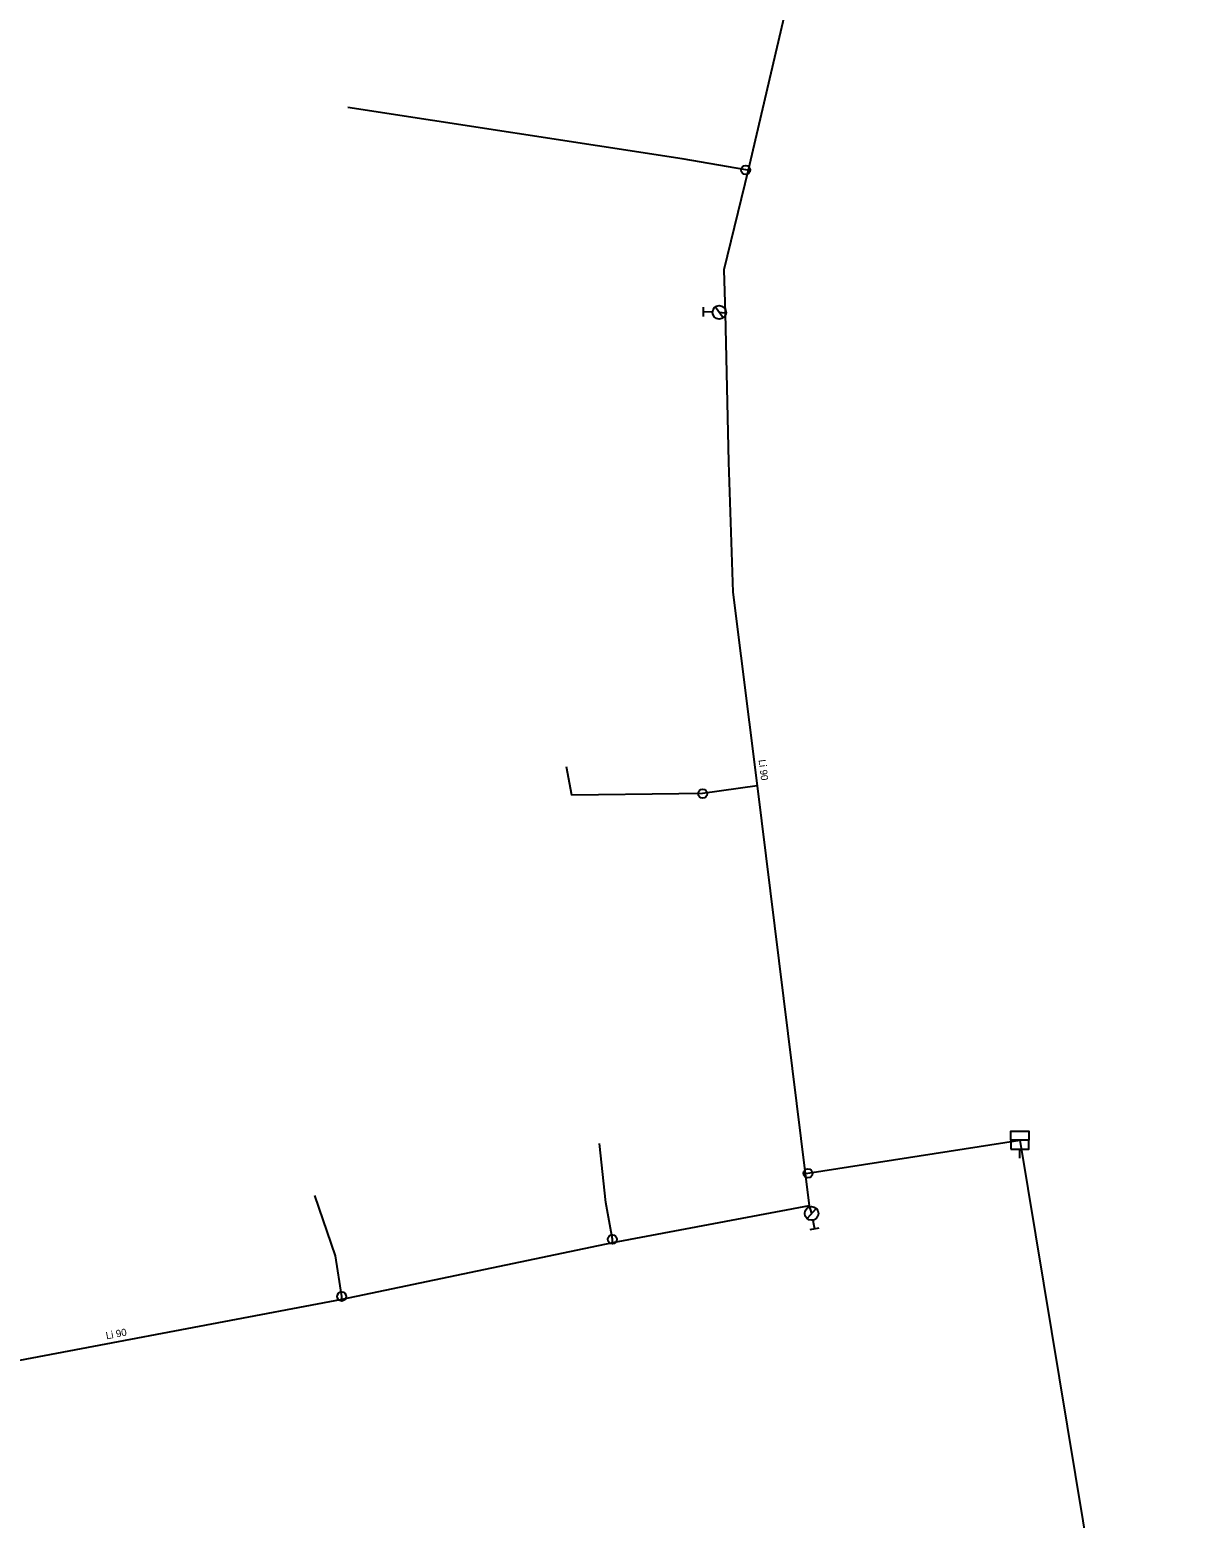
# Model space of a CAD drawing. Extents: x -684835 to -684548, y -1163297 to -1162881.
# Drawn here: x -684770.1 to -684705.3, y -1163230 to -1163147.7 of the extents above; entities that cross this region are included whole.
import ezdxf

# ---------------------------------------------------------------- set-up
doc = ezdxf.new("R2010")
doc.units = 0
for name, color, linetype in [('Hydranty', 7, 'Continuous'), ('Popis vodovodních řadů', 7, 'Continuous'), ('Vod přípojky-voda pitná', 7, 'Continuous'), ('Vodovodní řad', 7, 'Continuous'), ('Vodovodní šachty', 7, 'Continuous'), ('Vodovodní šoupata', 7, 'Continuous')]:
    doc.layers.add(name, color=color, linetype=linetype)

msp = doc.modelspace()

# ---------------------------------------------------------------- linework, layer by layer
at = {"layer": 'Hydranty'}
for p, q in [((-684732.832, -1163163.543), (-684732.817, -1163163.043)), ((-684731.728, -1163163.621), (-684732.173, -1163163.017)), ((-684732.325, -1163163.308), (-684732.825, -1163163.293)), ((-684726.602, -1163212.84), (-684727.1, -1163213.401)), ((-684726.448, -1163213.936), (-684726.94, -1163214.026)), ((-684726.783, -1163213.489), (-684726.694, -1163213.981))]:
    msp.add_line(p, q, dxfattribs=at)
for centre in [(-684731.95, -1163163.32), (-684726.85, -1163213.12)]:
    msp.add_circle(centre, 0.375, dxfattribs=at)
at = {"layer": 'Vod přípojky-voda pitná'}
for points in [[(-684734, -1163154.83), (-684752.48, -1163152)], [(-684730.36, -1163155.46), (-684730.49, -1163155.45), (-684734, -1163154.83)], [(-684734.19, -1163189.93), (-684740.1, -1163190), (-684740.39, -1163188.44)], [(-684729.85, -1163189.49), (-684732.87, -1163189.92), (-684734.19, -1163189.93)], [(-684738.22, -1163212.52), (-684738.58, -1163209.25)], [(-684727.2, -1163210.92), (-684727.05, -1163210.9), (-684715.34, -1163209.07), (-684705.31, -1163269.63), (-684711.55, -1163270.87)], [(-684753.16, -1163215.46), (-684754.31, -1163212.12)], [(-684737.79, -1163214.75), (-684737.85, -1163214.74), (-684737.86, -1163214.55), (-684738.22, -1163212.52)], [(-684752.81, -1163217.88), (-684752.82, -1163217.71), (-684753.16, -1163215.46)]]:
    msp.add_lwpolyline(points, dxfattribs=at)
at = {"layer": 'Vodovodní řad'}
for points in [[(-684705.98, -1163090.06), (-684706.95, -1163092.99), (-684710.58, -1163100.92), (-684712.51, -1163104.98), (-684716.99, -1163114.99), (-684720.87, -1163123.98), (-684725.19, -1163133.16), (-684725.44, -1163135.01), (-684726.52, -1163138.08), (-684728.3, -1163146.71), (-684730.36, -1163155.46), (-684731.69, -1163160.97), (-684731.63, -1163163.37)], [(-684731.63, -1163163.37), (-684731.95, -1163163.32)], [(-684731.63, -1163163.37), (-684731.45, -1163171.6), (-684731.2, -1163178.79), (-684729.85, -1163189.49), (-684727.2, -1163210.92), (-684726.98, -1163212.7)], [(-684726.98, -1163212.7), (-684737.85, -1163214.74), (-684752.81, -1163217.88), (-684774.44, -1163221.96), (-684804.55, -1163228.04)], [(-684726.98, -1163212.7), (-684726.85, -1163213.12)]]:
    msp.add_lwpolyline(points, dxfattribs=at)
at = {"layer": 'Vodovodní šachty'}
msp.add_line((-684715.34, -1163210.07), (-684715.34, -1163209.57), dxfattribs=at)
msp.add_lwpolyline([(-684715.84, -1163209.07), (-684715.84, -1163208.57), (-684714.84, -1163208.57), (-684714.84, -1163209.07)], dxfattribs=at)
msp.add_lwpolyline([(-684715.84, -1163209.57), (-684714.84, -1163209.57), (-684714.84, -1163209.07), (-684715.84, -1163209.07)], close=True, dxfattribs=at)
at = {"layer": 'Vodovodní šoupata'}
for centre in [(-684730.49, -1163155.45), (-684732.87, -1163189.92), (-684727.05, -1163210.9), (-684737.86, -1163214.55), (-684752.82, -1163217.71)]:
    msp.add_circle(centre, 0.25, dxfattribs=at)

# ---------------------------------------------------------------- texts
at = {"layer": 'Popis vodovodních řadů'}
for rotation, p in [(277.19091, (-684729.779, -1163188.058)), (10.68202, (-684765.819, -1163220.08))]:
    msp.add_text('Li 90', height=0.4, rotation=rotation, dxfattribs=at).set_placement(p)

doc.saveas('drawing.dxf')
